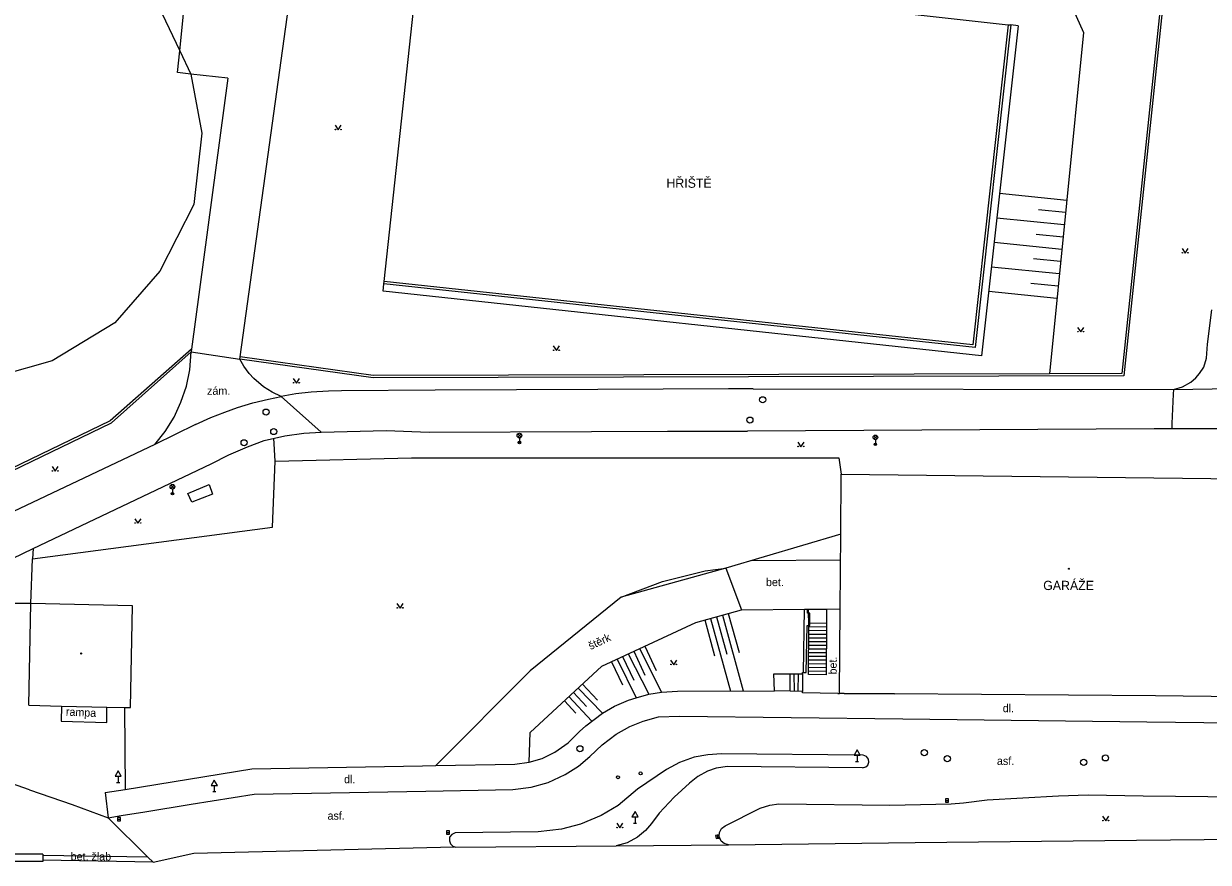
# Model space of a CAD drawing. Extents: x -602419 to -601554, y -1162937 to -1162362.
# Drawn here: x -602349.4 to -602253.1, y -1162714.8 to -1162646.7 of the extents above; entities that cross this region are included whole.
import ezdxf

# ---------------------------------------------------------------- set-up
doc = ezdxf.new("R2010")
doc.units = 0
doc.layers.add('Podklad', color=7, linetype='Continuous')

msp = doc.modelspace()

# ---------------------------------------------------------------- linework, layer by layer
at = {"layer": 'Podklad'}
for p, q in [((-602309.2425, -1162680.2899), (-602308.9775, -1162680.0249)), ((-602309.2425, -1162680.0249), (-602308.9775, -1162680.2899)), ((-602309.11, -1162680.3449), (-602309.11, -1162680.7199)), ((-602280.3225, -1162680.43), (-602280.0575, -1162680.165)), ((-602280.3225, -1162680.165), (-602280.0575, -1162680.43)), ((-602280.19, -1162680.485), (-602280.19, -1162680.86)), ((-602337.4325, -1162684.44), (-602337.1675, -1162684.175)), ((-602337.4325, -1162684.175), (-602337.1675, -1162684.44)), ((-602337.3, -1162684.495), (-602337.3, -1162684.87)), ((-602281.68, -1162706.121), (-602281.68, -1162706.63)), ((-602281.805, -1162706.63), (-602281.555, -1162706.63)), ((-602341.835, -1162708.33), (-602341.585, -1162708.33)), ((-602341.71, -1162707.821), (-602341.71, -1162708.33)), ((-602334.025, -1162709.07), (-602333.775, -1162709.07)), ((-602333.9, -1162708.561), (-602333.9, -1162709.07)), ((-602274.495, -1162709.79), (-602274.245, -1162709.79)), ((-602341.775, -1162711.31), (-602341.525, -1162711.31)), ((-602299.7199, -1162711.111), (-602299.7199, -1162711.62)), ((-602299.8449, -1162711.62), (-602299.5949, -1162711.62)), ((-602315.045, -1162712.39), (-602314.795, -1162712.39)), ((-602293.0461, -1162712.606), (-602293.0139, -1162712.854))]:
    msp.add_line(p, q, dxfattribs=at)
for points in [[(-602416.01, -1162611.55), (-602416.9699, -1162611.44), (-602417.7801, -1162618.6899), (-602418.9, -1162628.71), (-602419.4699, -1162637.42), (-602419.45, -1162641.75), (-602418.58, -1162646.04), (-602416.34, -1162654.4099), (-602405.02, -1162691.86), (-602365.76, -1162690.46), (-602342.26, -1162679.12), (-602335.78, -1162673.36)], [(-602335.75, -1162673.15), (-602342.37, -1162678.95), (-602365.81, -1162690.27), (-602404.87, -1162691.6599), (-602416.14, -1162654.36), (-602418.38, -1162646), (-602419.25, -1162641.73), (-602419.27, -1162637.43), (-602418.7, -1162628.7199), (-602416.8, -1162611.6599), (-602416.03, -1162611.75)], [(-602253.31, -1162613.67), (-602256.13, -1162638.49), (-602260, -1162675.31), (-602321, -1162675.4699), (-602331.82, -1162673.96)], [(-602340.91, -1162642.88), (-602338.17, -1162645.84), (-602336.71, -1162648.92), (-602335.81, -1162650.8), (-602334.91, -1162655.6), (-602335.55, -1162661.39), (-602338.33, -1162666.79), (-602341.98, -1162671), (-602347.06, -1162674.09), (-602351.26, -1162675.28), (-602355.87, -1162675.28), (-602392.78, -1162671.16), (-602397.78, -1162669.49), (-602400.24, -1162668.06), (-602403.1, -1162665.2), (-602405.72, -1162661.55), (-602407.46, -1162657.03), (-602408.02, -1162652.26), (-602407.38, -1162647.82), (-602405.56, -1162643.45), (-602402.94, -1162639.88), (-602400.24, -1162637.5), (-602399.17, -1162636.42)], [(-602317.78, -1162637.5), (-602278.15, -1162642.14), (-602267.72, -1162643.36), (-602264.36, -1162645), (-602263.28, -1162647.42), (-602266.06, -1162675.13)], [(-602256.33, -1162638.4699), (-602260.18, -1162675.11), (-602266.06, -1162675.13)], [(-602317.24, -1162641.54), (-602278.67, -1162645.77), (-602269.4, -1162646.79)], [(-602332.81, -1162651.12), (-602335.81, -1162650.8), (-602336.88, -1162650.68), (-602336.71, -1162648.92), (-602336.16, -1162643.41)], [(-602331.79, -1162673.76), (-602327.62, -1162643.61)], [(-602320.1, -1162667.64), (-602317.62, -1162644.58)], [(-602269.4, -1162646.79), (-602272.28, -1162672.79), (-602320.1, -1162667.64)], [(-602269.2, -1162646.81), (-602272.1, -1162673.01)], [(-602269.4, -1162646.79), (-602269.2, -1162646.81)], [(-602268.6, -1162646.88), (-602269.2, -1162646.81)], [(-602268.6, -1162646.88), (-602271.57, -1162673.67), (-602320.18, -1162668.43)], [(-602332.81, -1162651.12), (-602335.75, -1162673.15)], [(-602324.08, -1162654.955), (-602323.83, -1162655.33), (-602323.58, -1162654.955)], [(-602264.65, -1162661.05), (-602270.11, -1162660.5)], [(-602264.75, -1162662.05), (-602266.94, -1162661.83)], [(-602264.85, -1162663.04), (-602270.33, -1162662.49)], [(-602264.95, -1162664.04), (-602267.14, -1162663.82)], [(-602265.05, -1162665.03), (-602270.55, -1162664.48)], [(-602255.28, -1162664.955), (-602255.03, -1162665.33), (-602254.78, -1162664.955)], [(-602265.15, -1162666.03), (-602267.35, -1162665.81)], [(-602265.25, -1162667.02), (-602270.77, -1162666.4699)], [(-602320.18, -1162668.43), (-602320.12, -1162667.83)], [(-602320.12, -1162667.83), (-602320.1, -1162667.64)], [(-602272.1, -1162673.01), (-602320.12, -1162667.83)], [(-602265.35, -1162668.02), (-602267.56, -1162667.8)], [(-602265.45, -1162669.01), (-602270.99, -1162668.46)], [(-602253.21, -1162672.7199), (-602252.87, -1162669.93)], [(-602263.76, -1162671.365), (-602263.51, -1162671.74), (-602263.26, -1162671.365)], [(-602255.98, -1162676.4), (-602255.23, -1162676.2), (-602254.56, -1162675.82), (-602254.15, -1162675.4699), (-602253.85, -1162675.12), (-602253.52, -1162674.59), (-602253.29, -1162673.86), (-602253.21, -1162672.7199)], [(-602338.7199, -1162680.89), (-602337.88, -1162679.83), (-602337.17, -1162678.67), (-602336.61, -1162677.43), (-602336.17, -1162676.14), (-602335.9, -1162674.81), (-602335.78, -1162673.36)], [(-602335.75, -1162673.15), (-602335.78, -1162673.36)], [(-602335.78, -1162673.36), (-602331.82, -1162673.96)], [(-602331.82, -1162673.96), (-602331.79, -1162673.76)], [(-602266.06, -1162675.13), (-602321, -1162675.27), (-602331.79, -1162673.76)], [(-602306.36, -1162672.875), (-602306.11, -1162673.25), (-602305.86, -1162672.875)], [(-602328.46, -1162676.9699), (-602329.2, -1162676.62), (-602329.9, -1162676.19), (-602330.7, -1162675.51), (-602331.06, -1162675.11), (-602331.51, -1162674.51), (-602331.82, -1162673.96)], [(-602327.48, -1162675.515), (-602327.23, -1162675.89), (-602326.98, -1162675.515)], [(-602323.57, -1162676.51), (-602324.63, -1162676.54), (-602326.03, -1162676.63), (-602327.28, -1162676.77), (-602328.46, -1162676.9699)], [(-602315.96, -1162676.48), (-602323.57, -1162676.51)], [(-602302.74, -1162676.4099), (-602315.96, -1162676.48)], [(-602290.12, -1162676.37), (-602292.13, -1162676.36), (-602302.74, -1162676.4099)], [(-602290.12, -1162676.37), (-602255.98, -1162676.4)], [(-602255.98, -1162676.4), (-602255.9968, -1162676.7822), (-602256.1, -1162679.1619), (-602256.12, -1162679.62)], [(-602255.98, -1162676.4), (-602248.1, -1162676.28)], [(-602335.42, -1162679.25), (-602334.18, -1162678.7), (-602333.05, -1162678.24), (-602332.02, -1162677.88), (-602330.78, -1162677.5), (-602329.51, -1162677.2), (-602328.46, -1162676.9699)], [(-602325.2199, -1162679.87), (-602328.46, -1162676.9699)], [(-602335.42, -1162679.25), (-602338.7199, -1162680.89)], [(-602334.1599, -1162682.46), (-602332.71, -1162681.71), (-602331.21, -1162681.06), (-602329.86, -1162680.56), (-602328.1599, -1162680.17), (-602326.63, -1162679.9699), (-602325.2199, -1162679.87)], [(-602328.95, -1162682.24), (-602329.0637, -1162680.3773)], [(-602325.2199, -1162679.87), (-602319.94, -1162679.74), (-602316.45, -1162679.87)], [(-602316.45, -1162679.87), (-602303.26, -1162679.83)], [(-602303.26, -1162679.83), (-602297.07, -1162679.81)], [(-602297.07, -1162679.81), (-602292.62, -1162679.8), (-602290.59, -1162679.79)], [(-602230.21, -1162679.62), (-602251.43, -1162679.62), (-602257.55, -1162679.62), (-602290.59, -1162679.79)], [(-602338.7199, -1162680.89), (-602367.49, -1162694.49)], [(-602286.49, -1162680.685), (-602286.24, -1162681.06), (-602285.99, -1162680.685)], [(-602348.62, -1162689.33), (-602334.1599, -1162682.46)], [(-602329.1599, -1162687.59), (-602328.95, -1162682.24), (-602317.87, -1162681.9699), (-602283.15, -1162681.96), (-602282.98, -1162683.3)], [(-602347.08, -1162682.675), (-602346.83, -1162683.05), (-602346.58, -1162682.675)], [(-602283.01, -1162688.17), (-602282.98, -1162683.3)], [(-602282.98, -1162683.3), (-602243.71, -1162683.74)], [(-602336.06, -1162684.85), (-602334.33, -1162684.13), (-602334.05, -1162684.9), (-602335.73, -1162685.57), (-602336.06, -1162684.85)], [(-602340.35, -1162686.905), (-602340.1, -1162687.28), (-602339.85, -1162686.905)], [(-602348.6599, -1162690.17), (-602329.1599, -1162687.59)], [(-602283.01, -1162688.17), (-602292.35, -1162690.9099)], [(-602283.05, -1162694.23), (-602283.01, -1162688.17)], [(-602351.94, -1162690.9099), (-602348.62, -1162689.33)], [(-602348.62, -1162689.33), (-602348.6599, -1162690.17)], [(-602348.81, -1162693.8), (-602348.6599, -1162690.17)], [(-602292.35, -1162690.9099), (-602300.85, -1162693.27), (-602308.24, -1162699.26), (-602315.9, -1162706.96)], [(-602292.35, -1162690.9099), (-602300.85, -1162693.27), (-602308.24, -1162699.26), (-602315.9, -1162706.96)], [(-602300.85, -1162693.27), (-602297.497, -1162691.9939), (-602294.009, -1162691.1509), (-602292.35, -1162690.9099)], [(-602292.35, -1162690.9099), (-602291.08, -1162694.31)], [(-602290.27, -1162690.2997), (-602283.0236, -1162690.2362)], [(-602348.81, -1162693.8), (-602351.84, -1162693.8)], [(-602348.98, -1162702.05), (-602348.81, -1162693.8)], [(-602340.54, -1162693.99), (-602348.81, -1162693.8)], [(-602340.71, -1162702.24), (-602340.54, -1162693.99)], [(-602340.71, -1162702.24), (-602340.54, -1162693.99)], [(-602319.06, -1162693.795), (-602318.81, -1162694.17), (-602318.56, -1162693.795)], [(-602308.32, -1162706.67), (-602308.24, -1162704.26), (-602302.43, -1162698.89), (-602294.79, -1162695.33), (-602291.08, -1162694.31)], [(-602308.32, -1162706.67), (-602308.24, -1162704.26), (-602302.43, -1162698.89), (-602294.79, -1162695.33), (-602291.08, -1162694.31)], [(-602293.1, -1162694.87), (-602292.26, -1162697.9099)], [(-602292.62, -1162694.73), (-602290.93, -1162700.89)], [(-602292.14, -1162694.6), (-602291.26, -1162697.78)], [(-602291.08, -1162694.31), (-602285.95, -1162694.25)], [(-602286.03, -1162699.4), (-602285.95, -1162694.25)], [(-602285.95, -1162694.25), (-602285.71, -1162694.24)], [(-602285.7199, -1162694.59), (-602285.71, -1162694.24)], [(-602285.62, -1162694.59), (-602285.7199, -1162694.59)], [(-602285.71, -1162694.24), (-602285.62, -1162694.24)], [(-602285.62, -1162694.24), (-602284.17, -1162694.24)], [(-602285.62, -1162694.59), (-602285.62, -1162694.24)], [(-602285.61, -1162695.37), (-602285.62, -1162694.59)], [(-602285.51, -1162694.59), (-602285.62, -1162694.59)], [(-602285.52, -1162695.37), (-602285.51, -1162694.59)], [(-602284.17, -1162694.24), (-602283.05, -1162694.23)], [(-602284.17, -1162694.24), (-602284.1599, -1162695.39)], [(-602283.1, -1162701.1), (-602283.05, -1162694.23)], [(-602294.06, -1162695.13), (-602293.27, -1162698.04)], [(-602293.58, -1162695), (-602291.9699, -1162700.9)], [(-602285.81, -1162699.39), (-602285.74, -1162695.58)], [(-602285.74, -1162695.58), (-602285.61, -1162695.58)], [(-602284.1599, -1162695.39), (-602284.2, -1162699.58), (-602285.64, -1162699.57), (-602285.61, -1162695.58)], [(-602285.61, -1162695.58), (-602285.61, -1162695.37)], [(-602285.61, -1162695.37), (-602285.52, -1162695.37)], [(-602285.61, -1162695.58), (-602285.52, -1162695.58)], [(-602285.61, -1162695.67), (-602284.1599, -1162695.68)], [(-602285.52, -1162695.58), (-602285.52, -1162695.37)], [(-602285.52, -1162695.37), (-602284.1599, -1162695.39)], [(-602285.62, -1162696.57), (-602284.17, -1162696.58)], [(-602285.62, -1162696.87), (-602284.17, -1162696.88)], [(-602285.61, -1162695.9699), (-602284.1599, -1162695.98)], [(-602285.61, -1162696.27), (-602284.17, -1162696.28)], [(-602299.82, -1162697.67), (-602298.9099, -1162699.62)], [(-602299.37, -1162697.46), (-602297.58, -1162700.99)], [(-602298.9099, -1162697.25), (-602297.99, -1162699.23)], [(-602285.63, -1162697.77), (-602284.18, -1162697.78)], [(-602285.62, -1162697.17), (-602284.18, -1162697.18)], [(-602285.62, -1162697.4699), (-602284.18, -1162697.48)], [(-602301.63, -1162698.52), (-602300.75, -1162700.4)], [(-602301.18, -1162698.31), (-602299.62, -1162701.44)], [(-602300.73, -1162698.1), (-602299.83, -1162700.01)], [(-602300.27, -1162697.89), (-602298.6, -1162701.1599)], [(-602296.83, -1162698.385), (-602296.58, -1162698.76), (-602296.33, -1162698.385)], [(-602285.63, -1162698.07), (-602284.18, -1162698.08)], [(-602285.63, -1162698.37), (-602284.19, -1162698.38)], [(-602285.63, -1162698.67), (-602284.19, -1162698.68)], [(-602288.39, -1162700.89), (-602288.43, -1162699.5), (-602287.11, -1162699.5)], [(-602287.12, -1162700.9099), (-602287.11, -1162699.5)], [(-602287.11, -1162699.5), (-602286.11, -1162699.51)], [(-602286.77, -1162700.92), (-602286.79, -1162699.51)], [(-602286.46, -1162700.92), (-602286.45, -1162699.51)], [(-602286.11, -1162699.51), (-602286.12, -1162700.93)], [(-602286.11, -1162699.51), (-602286.11, -1162699.4), (-602286.03, -1162699.4)], [(-602286.03, -1162699.4), (-602285.81, -1162699.39)], [(-602285.64, -1162699.27), (-602284.19, -1162699.28)], [(-602285.63, -1162698.9699), (-602284.19, -1162698.98)], [(-602304.35, -1162700.67), (-602302.35, -1162702.71)], [(-602303.99, -1162700.33), (-602302.78, -1162701.63)], [(-602305.45, -1162701.69), (-602304.53, -1162702.69)], [(-602305.09, -1162701.35), (-602303.23, -1162703.34)], [(-602304.7199, -1162701.01), (-602303.6599, -1162702.1599)], [(-602304.23, -1162704.2), (-602303.71, -1162703.74), (-602302.35, -1162702.71), (-602301.4, -1162702.14), (-602300.24, -1162701.65), (-602299.62, -1162701.44), (-602298.6, -1162701.1599), (-602297.58, -1162700.99), (-602296.26, -1162700.9099)], [(-602297.8, -1162703), (-602296.1, -1162702.93), (-602277.9699, -1162703.17), (-602258.14, -1162703.4099), (-602244.23, -1162703.56), (-602243.24, -1162703.37), (-602242.42, -1162702.9699), (-602241.63, -1162702.26), (-602241.14, -1162701.4699)], [(-602296.26, -1162700.9099), (-602288.39, -1162700.89)], [(-602287.12, -1162700.9099), (-602288.39, -1162700.89)], [(-602286.12, -1162700.93), (-602287.12, -1162700.9099)], [(-602283.25, -1162701.09), (-602286.12, -1162701.05), (-602286.12, -1162700.93)], [(-602283.25, -1162701.09), (-602283.1, -1162701.1)], [(-602282.7199, -1162701.1), (-602283.1, -1162701.1)], [(-602278.65, -1162701.14), (-602282.7199, -1162701.1)], [(-602282.7199, -1162701.1), (-602278.65, -1162701.14)], [(-602257.45, -1162701.28), (-602278.65, -1162701.14)], [(-602243.89, -1162701.45), (-602257.45, -1162701.28)], [(-602348.98, -1162702.05), (-602346.31, -1162702.12)], [(-602346.31, -1162702.12), (-602346.34, -1162703.36), (-602342.63, -1162703.4699), (-602342.62, -1162702.2199)], [(-602346.31, -1162702.12), (-602342.62, -1162702.2199)], [(-602342.62, -1162702.2199), (-602341.2, -1162702.23), (-602340.71, -1162702.24)], [(-602342.62, -1162702.2199), (-602341.2, -1162702.23), (-602340.71, -1162702.24)], [(-602341.2, -1162702.23), (-602341.15, -1162708.89)], [(-602341.2, -1162702.23), (-602341.15, -1162708.89)], [(-602342.51, -1162711.19), (-602341.4699, -1162711.02), (-602339.53, -1162710.7), (-602335.77, -1162710.09), (-602330.67, -1162709.29), (-602316.7199, -1162709.04), (-602309.6599, -1162708.9), (-602308.17, -1162708.71), (-602306.78, -1162708.32), (-602305.39, -1162707.69), (-602304.31, -1162707), (-602303.38, -1162706.23), (-602302.39, -1162705.26), (-602301.25, -1162704.4099), (-602300.14, -1162703.79), (-602299.07, -1162703.35), (-602297.8, -1162703)], [(-602342.51, -1162711.19), (-602341.4699, -1162711.02), (-602339.53, -1162710.7), (-602335.77, -1162710.09), (-602330.67, -1162709.29), (-602316.7199, -1162709.04), (-602309.6599, -1162708.9), (-602308.17, -1162708.71), (-602306.78, -1162708.32), (-602305.39, -1162707.69), (-602304.31, -1162707), (-602303.38, -1162706.23), (-602302.39, -1162705.26), (-602301.25, -1162704.4099), (-602300.14, -1162703.79), (-602299.07, -1162703.35), (-602297.8, -1162703)], [(-602308.32, -1162706.67), (-602307.26, -1162706.38), (-602306.24, -1162705.87), (-602305.14, -1162705.1), (-602304.23, -1162704.2)], [(-602308.32, -1162706.67), (-602307.26, -1162706.38), (-602306.24, -1162705.87), (-602305.14, -1162705.1), (-602304.23, -1162704.2)], [(-602292.69, -1162706.01), (-602293.8, -1162706.08), (-602294.92, -1162706.27), (-602296.11, -1162706.7), (-602297.1599, -1162707.27), (-602299.52, -1162708.88), (-602301.1, -1162710.19)], [(-602281.23, -1162707.13), (-602280.98, -1162707.07), (-602280.81, -1162706.9099), (-602280.7199, -1162706.67), (-602280.74, -1162706.44), (-602280.9099, -1162706.2199), (-602281.19, -1162706.11), (-602292.69, -1162706.01)], [(-602281.23, -1162707.13), (-602280.98, -1162707.07), (-602280.81, -1162706.9099), (-602280.7199, -1162706.67), (-602280.74, -1162706.44), (-602280.9099, -1162706.2199), (-602281.19, -1162706.11), (-602292.69, -1162706.01)], [(-602342.76, -1162709.14), (-602341.69, -1162708.98), (-602341.15, -1162708.89), (-602330.85, -1162707.23), (-602316.98, -1162706.98), (-602315.9, -1162706.96)], [(-602315.9, -1162706.96), (-602309.48, -1162706.84), (-602308.32, -1162706.67)], [(-602281.23, -1162707.13), (-602292.2199, -1162707.02), (-602293.13, -1162707.17), (-602293.83, -1162707.4099), (-602294.62, -1162707.84), (-602295.3, -1162708.38)], [(-602348.9099, -1162708.92), (-602352.7, -1162707.61)], [(-602295.3, -1162708.38), (-602296.53, -1162709.51), (-602297.76, -1162710.82), (-602298.38, -1162711.67), (-602298.88, -1162712.24), (-602299.53, -1162712.77), (-602300.37, -1162713.2199), (-602301.25, -1162713.48)], [(-602348.9099, -1162708.92), (-602345.44, -1162710.12), (-602342.51, -1162711.19)], [(-602342.76, -1162709.14), (-602342.51, -1162711.19)], [(-602292.13, -1162713.38), (-602292.48, -1162713.28), (-602292.7199, -1162713.1), (-602292.88, -1162712.7199), (-602292.87, -1162712.39), (-602292.7, -1162712.06), (-602292.4, -1162711.84), (-602289.55, -1162710.42), (-602288.77, -1162710.18), (-602288.04, -1162710.06), (-602279.01, -1162710.1599), (-602274.04, -1162710.05), (-602273.04, -1162709.9699), (-602271.12, -1162709.75), (-602265.33, -1162709.4099), (-602262.9, -1162709.33), (-602258.44, -1162709.4)], [(-602258.44, -1162709.4), (-602245.33, -1162709.54), (-602244.31, -1162709.46), (-602242.69, -1162709.07), (-602240.86, -1162708.88), (-602238.04, -1162708.8), (-602234.38, -1162708.6599), (-602230.35, -1162708.64), (-602220.05, -1162709.03), (-602205.43, -1162709.57)], [(-602301.1, -1162710.19), (-602302.4699, -1162711.01), (-602304.1599, -1162711.7199), (-602305.68, -1162712.12), (-602307.58, -1162712.33), (-602314.32, -1162712.4099), (-602314.59, -1162712.54), (-602314.78, -1162712.78), (-602314.8, -1162713.06), (-602314.71, -1162713.32), (-602314.53, -1162713.5), (-602314.27, -1162713.59)], [(-602339.31, -1162714.4), (-602342.51, -1162711.19)], [(-602261.73, -1162711.075), (-602261.48, -1162711.45), (-602261.23, -1162711.075)], [(-602301.2, -1162711.645), (-602300.95, -1162712.02), (-602300.7, -1162711.645)], [(-602292.13, -1162713.38), (-602276.96, -1162713.21), (-602258.98, -1162713.02), (-602239.7, -1162712.81), (-602219.79, -1162712.59), (-602201.24, -1162712.43)], [(-602347.82, -1162714.15), (-602360.4099, -1162714.1599)], [(-602347.82, -1162714.15), (-602347.82, -1162714.25)], [(-602338.86, -1162714.81), (-602335.57, -1162714.0599), (-602314.4002, -1162713.5449)], [(-602314.27, -1162713.59), (-602301.25, -1162713.48)], [(-602301.25, -1162713.48), (-602292.13, -1162713.38)], [(-602347.82, -1162714.75), (-602365.34, -1162714.75)], [(-602347.82, -1162714.25), (-602347.82, -1162714.45), (-602347.82, -1162714.65)], [(-602338.86, -1162714.81), (-602339.31, -1162714.4), (-602347.82, -1162714.25)], [(-602338.86, -1162714.81), (-602347.82, -1162714.65)], [(-602347.82, -1162714.65), (-602347.82, -1162714.75)]]:
    msp.add_lwpolyline(points, dxfattribs=at)
for points in [[(-602281.93, -1162706.121), (-602281.43, -1162706.121), (-602281.68, -1162705.688)], [(-602341.96, -1162707.821), (-602341.46, -1162707.821), (-602341.71, -1162707.388)], [(-602334.15, -1162708.561), (-602333.65, -1162708.561), (-602333.9, -1162708.128)], [(-602274.495, -1162709.915), (-602274.245, -1162709.915), (-602274.245, -1162709.665), (-602274.495, -1162709.665)], [(-602341.775, -1162711.435), (-602341.525, -1162711.435), (-602341.525, -1162711.185), (-602341.775, -1162711.185)], [(-602299.9699, -1162711.111), (-602299.4699, -1162711.111), (-602299.7199, -1162710.678)], [(-602315.045, -1162712.515), (-602314.795, -1162712.515), (-602314.795, -1162712.265), (-602315.045, -1162712.265)], [(-602293.1701, -1162712.6221), (-602293.1379, -1162712.8701), (-602292.8899, -1162712.8379), (-602292.9221, -1162712.5899)]]:
    msp.add_lwpolyline(points, close=True, dxfattribs=at)
for centre, radius in [((-602324.0551, -1162655.3049), 0.025), ((-602323.6054, -1162655.3049), 0.025), ((-602255.2551, -1162665.3049), 0.025), ((-602254.8054, -1162665.3049), 0.025), ((-602263.7351, -1162671.7149), 0.025), ((-602263.2854, -1162671.7149), 0.025), ((-602306.3351, -1162673.2249), 0.025), ((-602305.8854, -1162673.2249), 0.025), ((-602327.4551, -1162675.8649), 0.025), ((-602327.0054, -1162675.8649), 0.025), ((-602289.35, -1162677.25), 0.25), ((-602329.69, -1162678.25), 0.25), ((-602329.07, -1162679.83), 0.25), ((-602290.39, -1162678.9), 0.25), ((-602331.48, -1162680.74), 0.25), ((-602309.11, -1162680.1574), 0.1875), ((-602280.19, -1162680.2975), 0.1875), ((-602309.11, -1162680.7199), 0.1), ((-602309.11, -1162680.7199), 0.0723), ((-602309.11, -1162680.7199), 0.0438), ((-602286.4651, -1162681.0349), 0.025), ((-602286.0154, -1162681.0349), 0.025), ((-602280.19, -1162680.86), 0.1), ((-602280.19, -1162680.86), 0.0723), ((-602280.19, -1162680.86), 0.0438), ((-602347.0551, -1162683.0249), 0.025), ((-602346.6054, -1162683.0249), 0.025), ((-602337.3, -1162684.3075), 0.1875), ((-602337.3, -1162684.87), 0.1), ((-602337.3, -1162684.87), 0.0723), ((-602337.3, -1162684.87), 0.0438), ((-602340.3251, -1162687.2549), 0.025), ((-602339.8754, -1162687.2549), 0.025), ((-602264.4699, -1162690.9699), 0.045), ((-602264.4699, -1162690.9699), 0.0199), ((-602319.0351, -1162694.1449), 0.025), ((-602318.5854, -1162694.1449), 0.025), ((-602344.7199, -1162697.85), 0.045), ((-602344.7199, -1162697.85), 0.0199), ((-602296.8051, -1162698.7349), 0.025), ((-602296.3554, -1162698.7349), 0.025), ((-602304.2, -1162705.59), 0.25), ((-602276.2199, -1162705.9099), 0.25), ((-602274.35, -1162706.4), 0.25), ((-602263.27, -1162706.69), 0.25), ((-602261.5, -1162706.33), 0.25), ((-602299.27, -1162707.59), 0.125), ((-602301.11, -1162707.9), 0.125), ((-602301.1751, -1162711.9949), 0.025), ((-602300.7254, -1162711.9949), 0.025), ((-602261.7051, -1162711.4249), 0.025), ((-602261.2554, -1162711.4249), 0.025)]:
    msp.add_circle(centre, radius, dxfattribs=at)

# ---------------------------------------------------------------- texts
for s, height, p in [('HŘIŠTĚ', 0.75, (-602297.17, -1162660.03)), (' zám.', 0.65, (-602334.73, -1162676.84)), ('bet.', 0.65, (-602289.08, -1162692.38)), ('GARÁŽE', 0.75, (-602266.56, -1162692.7)), (' dl.', 0.65, (-602270.09, -1162702.62)), (' asf.', 0.65, (-602270.56, -1162706.9)), (' dl.', 0.65, (-602323.6, -1162708.39)), (' asf.', 0.65, (-602324.94, -1162711.35))]:
    msp.add_text(s, height=height, dxfattribs=at).set_placement(p)
for s, rotation, p in [('štěrk', 24.98, (-602303.33, -1162697.57)), ('bet.', 89.44, (-602283.34, -1162699.56)), ('rampa', 357.21, (-602345.9699, -1162702.89)), ('bet. žlab', 359.68, (-602345.57, -1162714.65))]:
    msp.add_text(s, height=0.65, rotation=rotation, dxfattribs=at).set_placement(p)

doc.saveas('drawing.dxf')
